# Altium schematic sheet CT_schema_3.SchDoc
size 308 x 312 mm
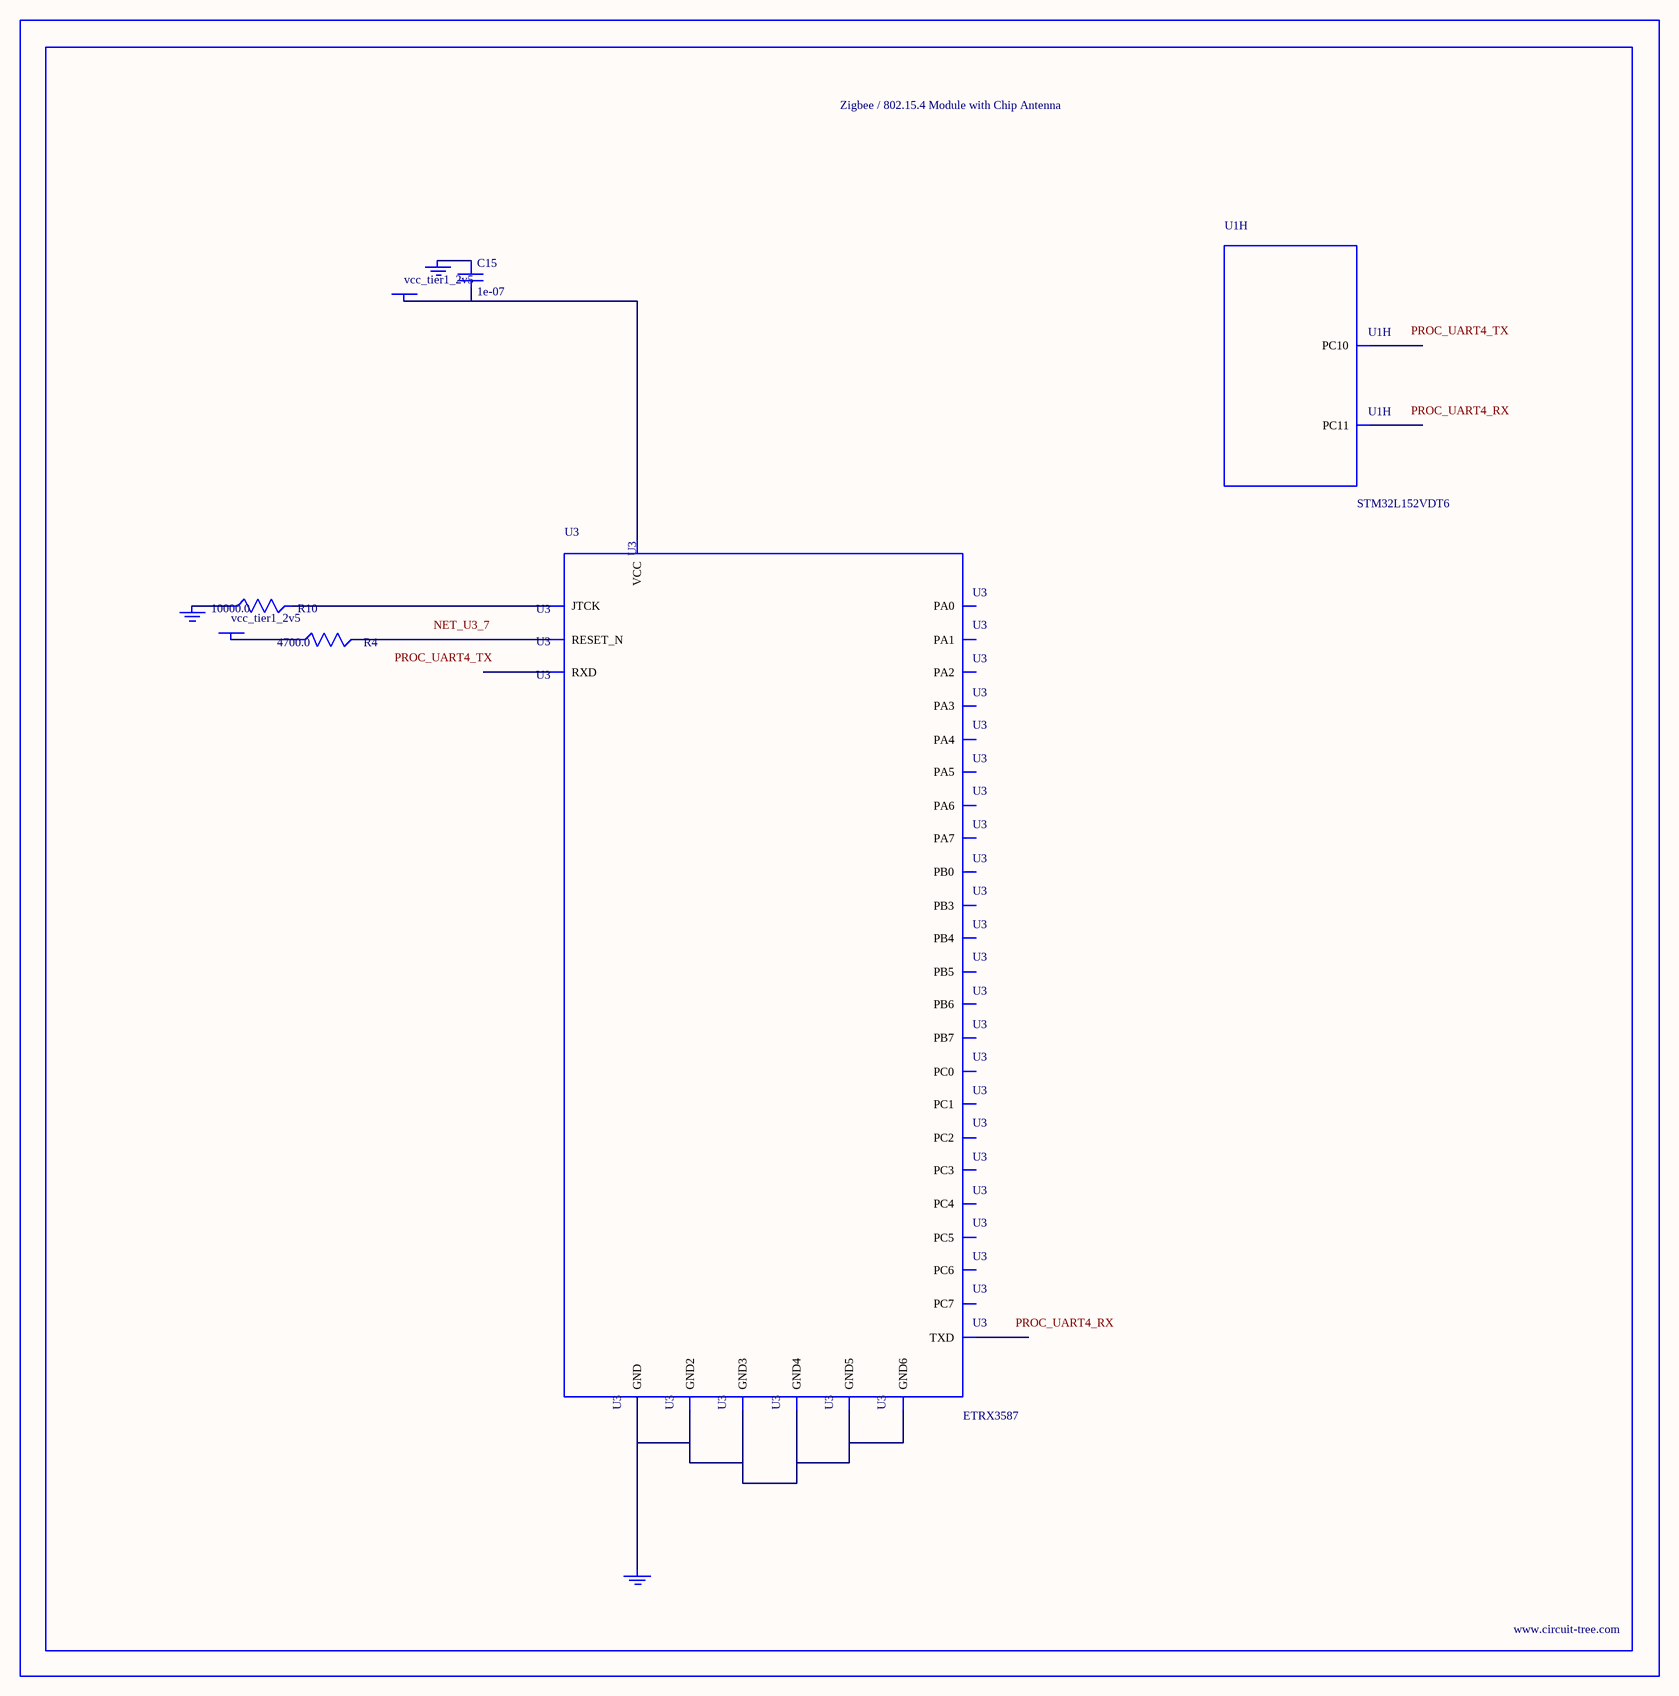
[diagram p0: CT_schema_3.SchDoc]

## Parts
BORDER2  (no value)
C15  1e-07  [C0402]
GND_INSTANCE_2_0  (no value)
GND_INSTANCE_2_1  (no value)
GND_INSTANCE_2_2  (no value)
POWER_INSTANCE_2_0  vcc_tier1_2v5
POWER_INSTANCE_2_1  vcc_tier1_2v5
R4  4700.0  [R0603]
R10  10000.0  [R0603]
U1  STM32L152VDT6  [LQFP100]  (part H of 10)
U3  ETRX3587  [ETRX3587]

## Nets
NetC15_1: C15.1 GND_INSTANCE_2_1.0(GND)
NetC15_2: C15.2 POWER_INSTANCE_2_0.0(PWR) U3.32(VCC)
NetGND_INSTANCE_2_0_0: GND_INSTANCE_2_0.0(GND) R10.1
NetGND_INSTANCE_2_2_0: GND_INSTANCE_2_2.0(GND) U3.1(GND) U3.13(GND2) U3.19(GND3) U3.20(GND4) U3.31(GND5) U3.33(GND6)
NetPOWER_INSTANCE_2_1_0: POWER_INSTANCE_2_1.0(PWR) R4.1
NetR4_2: R4.2 U3.7(RESET_N)
NetR10_2: R10.2 U3.21(JTCK)

Not connected (* = marked no-connect by the designer): U1 78(PC10) 79(PC11); U3 2(PC5) 3(PC6) 4(PC7) 5(PA7) 6(PB3) 8(PB4) 9(PA0) 10(PA1) 11(PA2) 12(PA3) 14(PA4) 15(PA5) 16(PA6) 17(TXD) 18(RXD) 22(PC2) 23(PC3) 24(PC4) 25(PB0) 26(PC1) 27(PC0) 28(PB7) 29(PB6) 30(PB5)

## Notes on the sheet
- Labels drawn without touching a wire or pin: NET_U3_7, PROC_UART4_RX, PROC_UART4_TX

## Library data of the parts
BORDER2 = BORDER_PAGE2
C15 = C0402C104K3RACTU
GND_INSTANCE_2_0-GND_INSTANCE_2_2 = GND
POWER_INSTANCE_2_0 POWER_INSTANCE_2_1 = PWR
R4 = RC0603JR-074K7L
R10 = RC0603JR-0710KL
